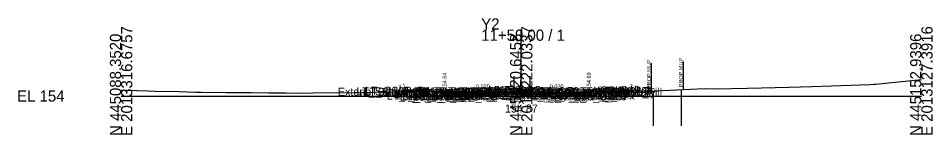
# Model space of a CAD drawing. Extents: x -26 to 203, y -10 to 6017.
# Drawn here: x -25.7 to 202.8, y 2990.3 to 3019.5 of the extents above; entities that cross this region are included whole.
import ezdxf

# ---------------------------------------------------------------- set-up
doc = ezdxf.new("R2010")
doc.units = 0
for name, color, linetype in [('Default', 7, 'Continuous'), ('Exist CMT Pavement', 7, 'Continuous'), ('Exist Cross Section Cell', 7, 'Continuous'), ('Exist XS Center Line Elevation Label', 7, 'Continuous'), ('Exist XS Ground Line', 7, 'Continuous'), ('Prop CMT Conc Surface', 7, 'Continuous'), ('Prop CMT Concrete Structures', 7, 'Continuous'), ('Prop CMT Pvmt Course 1', 7, 'Continuous'), ('Prop CMT Pvmt Course 1 CG', 7, 'Continuous'), ('Prop CMT Pvmt Course 1 Wedge', 7, 'Continuous'), ('Prop CMT Pvmt Course 2', 7, 'Continuous'), ('Prop CMT Pvmt Course 3', 7, 'Continuous'), ('Prop CMT Pvmt Surface', 7, 'Continuous'), ('Prop CMT Pvmt Wedge Surface 1', 7, 'Continuous'), ('Prop CMT Pvmt Wedge Surface 2', 7, 'Continuous'), ('Prop CMT Pvmt Wedge Surface 3', 7, 'Continuous'), ('Prop CMT Slope Grass', 7, 'Continuous'), ('Prop CMT Subgrade Earthwork', 7, 'Continuous'), ('Prop XS Earthwork Shape', 7, 'Continuous'), ('Prop XS Hydro Elevations', 7, 'Continuous'), ('Prop XS Label Text', 7, 'Continuous'), ('Prop XS SE Text', 7, 'Continuous'), ('Prop XS Side Slope Text', 7, 'Continuous'), ('Scratch_Level_0', 7, 'Continuous'), ('Scratch_Level_1', 7, 'Continuous'), ('Scratch_Level_3', 7, 'Continuous')]:
    doc.layers.add(name, color=color, linetype=linetype)

msp = doc.modelspace()

# ---------------------------------------------------------------- linework, layer by layer
at = {"layer": 'Exist CMT Pavement'}
for points in [[(98.12, 3000.89), (94.75, 3000.92), (94.58, 3000.92), (94.58, 3000.92)], [(102.81, 3000.85), (104.54, 3000.84), (113.53, 3000.87), (113.89, 3000.87)]]:
    msp.add_lwpolyline(points, dxfattribs=at)
at = {"layer": 'Exist Cross Section Cell'}
for p, q in [((100, 3000), (100, 3016.62)), ((0, 3000), (100, 3000)), ((100, 3000), (200, 3000))]:
    msp.add_line(p, q, dxfattribs=at)
at = {"layer": 'Exist XS Ground Line'}
msp.add_lwpolyline([(0, 3001.46), (1.27, 3001.43), (6.63, 3001.26), (8.46, 3001.2), (14.51, 3001.1), (18.68, 3000.96), (19.18, 3000.95), (20.04, 3000.95), (26.33, 3000.85), (27.65, 3000.85), (32.51, 3000.84), (36.8, 3000.76), (41.05, 3000.77), (44.21, 3000.75), (48, 3000.77), (60.19, 3000.87), (61.79, 3000.9), (63.21, 3000.94), (69.67, 3001.06), (71.87, 3001.1), (77.54, 3001.08), (92.24, 3001.2), (92.71, 3001.2), (94.58, 3000.92), (100, 3000.87), (104.54, 3000.84), (113.53, 3000.87), (114.15, 3000.87), (116.11, 3001.12), (116.88, 3001.12), (122.29, 3001.02), (123.96, 3001.02), (129.63, 3001.02), (135.36, 3001.36), (145.84, 3001.86), (148.45, 3001.82), (156.56, 3001.93), (166.97, 3002.21), (172.6, 3002.42), (177.54, 3002.56), (187.09, 3002.9), (188.11, 3002.94), (188.58, 3002.99), (200, 3004.17)], dxfattribs=at)
at = {"layer": 'Prop CMT Conc Surface'}
for points in [[(80.83, 3000.64), (80.83, 3001.14), (80.33, 3001.14)], [(82.83, 3000.76), (80.83, 3000.64)], [(114.89, 3000.81), (116.89, 3000.69)], [(116.89, 3000.69), (116.89, 3001.19), (117.39, 3001.19)]]:
    msp.add_lwpolyline(points, dxfattribs=at)
at = {"layer": 'Prop CMT Concrete Structures'}
for p, q in [((98.23, 3001.24), (98.22, 3001.07)), ((98.98, 3001.49), (98.23, 3001.24)), ((100.33, 3001.51), (98.98, 3001.49)), ((101.47, 3001.48), (100.33, 3001.51)), ((102.22, 3001.23), (101.47, 3001.48)), ((102.23, 3001.06), (102.22, 3001.23))]:
    msp.add_line(p, q, dxfattribs=at)
for points in [[(82.83, 3000.76), (80.83, 3000.64), (80.83, 3001.14), (80.33, 3001.14)], [(80.33, 3001.14), (80.33, 3000.13), (82.83, 3000.18)], [(82.83, 3000.18), (82.83, 3000.76)], [(98.22, 3001.07), (102.23, 3001.06)], [(114.89, 3000.81), (116.89, 3000.69), (116.89, 3001.19), (117.39, 3001.19)], [(117.39, 3001.19), (117.39, 3000.17), (114.89, 3000.22)], [(114.89, 3000.22), (114.89, 3000.81)]]:
    msp.add_lwpolyline(points, dxfattribs=at)
at = {"layer": 'Prop CMT Pvmt Course 1'}
for points in [[(98.22, 3001.07), (82.83, 3000.76)], [(82.83, 3000.76), (82.83, 3000.51)], [(82.83, 3000.51), (94.58, 3000.75)], [(94.58, 3000.87), (98.22, 3000.94)], [(94.58, 3000.75), (94.58, 3000.87)], [(98.22, 3000.82), (98.22, 3001.07)], [(98.22, 3001.07), (102.23, 3001.06)], [(98.22, 3000.82), (98.22, 3001.07)], [(98.22, 3000.94), (98.22, 3000.82), (98.22, 3000.82)], [(102.23, 3001.06), (114.89, 3000.81)], [(102.23, 3000.81), (102.23, 3001.06)], [(102.23, 3001.06), (102.23, 3000.81)], [(113.89, 3000.7), (102.23, 3000.93)], [(102.23, 3000.93), (102.23, 3000.81), (102.23, 3000.81)], [(113.89, 3000.58), (113.89, 3000.7)], [(114.89, 3000.81), (114.89, 3000.56)], [(114.89, 3000.56), (113.89, 3000.58)]]:
    msp.add_lwpolyline(points, dxfattribs=at)
at = {"layer": 'Prop CMT Pvmt Course 1 CG'}
for p, q in [((79.58, 2999.86), (82.83, 2999.84)), ((118.15, 2999.91), (114.89, 2999.89))]:
    msp.add_line(p, q, dxfattribs=at)
for points in [[(82.83, 3000.18), (79.83, 3000.12), (79.58, 2999.86)], [(82.83, 2999.93), (82.83, 3000.18)], [(114.89, 3000.22), (117.89, 3000.16), (118.15, 2999.91)], [(114.89, 2999.97), (114.89, 3000.22)]]:
    msp.add_lwpolyline(points, dxfattribs=at)
at = {"layer": 'Prop CMT Pvmt Course 1 Wedge'}
for points in [[(96.23, 3000.9), (98.12, 3000.94)], [(98.12, 3000.89), (96.23, 3000.9)], [(98.22, 3000.94), (98.22, 3000.89)], [(102.23, 3000.86), (102.23, 3000.93)], [(102.81, 3000.92), (104.54, 3000.89), (106.78, 3000.84)], [(106.78, 3000.84), (104.54, 3000.84), (102.81, 3000.85)]]:
    msp.add_lwpolyline(points, dxfattribs=at)
at = {"layer": 'Prop CMT Pvmt Course 2'}
for points in [[(92.71, 3000.71), (82.83, 3000.51)], [(94.58, 3000.41), (94.58, 3000.75)], [(98.22, 3000.49), (98.22, 3000.82)], [(102.23, 3000.81), (102.23, 3000.48)], [(82.83, 3000.51), (82.83, 3000.18)], [(82.83, 3000.18), (92.71, 3000.38)], [(113.89, 3000.24), (113.89, 3000.58)], [(113.89, 3000.58), (114.89, 3000.56)], [(114.89, 3000.22), (113.89, 3000.24)], [(114.89, 3000.56), (114.89, 3000.22)]]:
    msp.add_lwpolyline(points, dxfattribs=at)
at = {"layer": 'Prop CMT Pvmt Course 3'}
for points in [[(94.58, 3000.41), (82.83, 3000.18)], [(82.83, 3000.18), (82.83, 2999.84)], [(82.83, 2999.84), (94.58, 3000.08)], [(94.58, 3000.08), (94.58, 3000.41)], [(113.89, 3000.24), (114.89, 3000.22)], [(113.89, 2999.91), (113.89, 3000.24)], [(114.89, 2999.89), (113.89, 2999.91)], [(114.89, 3000.22), (114.89, 2999.89)]]:
    msp.add_lwpolyline(points, dxfattribs=at)
at = {"layer": 'Prop CMT Pvmt Surface'}
for points in [[(98.22, 3001.07), (82.83, 3000.76)], [(98.22, 3001.07), (102.23, 3001.06)], [(102.23, 3001.06), (114.89, 3000.81)]]:
    msp.add_lwpolyline(points, dxfattribs=at)
at = {"layer": 'Prop CMT Pvmt Wedge Surface 1'}
for points in [[(82.83, 3000.51), (82.83, 3000.76)], [(82.83, 3000.51), (82.83, 3000.76)], [(92.71, 3000.71), (82.83, 3000.51)], [(92.71, 3000.71), (82.83, 3000.51)], [(98.22, 3000.94), (94.58, 3000.87)], [(98.22, 3000.94), (94.58, 3000.87)], [(94.58, 3000.87), (94.58, 3000.75)], [(94.58, 3000.87), (94.58, 3000.75)], [(98.22, 3001.07), (98.22, 3000.82), (98.22, 3000.82), (98.22, 3000.94)], [(102.23, 3001.06), (102.23, 3000.81), (102.23, 3000.81), (102.23, 3000.93)], [(102.23, 3000.93), (113.89, 3000.7)], [(102.23, 3000.93), (113.89, 3000.7)], [(113.89, 3000.7), (113.89, 3000.58)], [(113.89, 3000.7), (113.89, 3000.58)], [(114.89, 3000.56), (114.89, 3000.81)], [(114.89, 3000.56), (114.89, 3000.81)], [(113.89, 3000.58), (114.89, 3000.56)], [(113.89, 3000.58), (114.89, 3000.56)]]:
    msp.add_lwpolyline(points, dxfattribs=at)
at = {"layer": 'Prop CMT Pvmt Wedge Surface 2'}
for points in [[(82.83, 3000.51), (82.83, 3000.76)], [(82.83, 3000.51), (82.83, 3000.76)], [(98.22, 3000.82), (94.58, 3000.75)], [(98.22, 3000.82), (94.58, 3000.75)], [(98.22, 3001.07), (98.22, 3000.82)], [(102.23, 3000.81), (98.22, 3000.82)], [(102.23, 3001.06), (102.23, 3000.81)], [(102.23, 3000.81), (114.89, 3000.56)], [(102.23, 3000.81), (114.89, 3000.56)], [(114.89, 3000.56), (114.89, 3000.81)], [(114.89, 3000.56), (114.89, 3000.81)]]:
    msp.add_lwpolyline(points, dxfattribs=at)
at = {"layer": 'Prop CMT Pvmt Wedge Surface 3'}
for points in [[(82.83, 3000.18), (82.83, 3000.76)], [(82.83, 3000.18), (82.83, 3000.76)], [(98.22, 3001.07), (98.22, 3000.49)], [(102.23, 3001.06), (102.23, 3000.48)], [(114.89, 3000.22), (114.89, 3000.81)], [(114.89, 3000.22), (114.89, 3000.81)], [(98.22, 3000.49), (94.58, 3000.41)], [(98.22, 3000.49), (94.58, 3000.41)], [(102.23, 3000.48), (98.22, 3000.49)], [(102.23, 3000.48), (114.89, 3000.22)], [(102.23, 3000.48), (114.89, 3000.22)]]:
    msp.add_lwpolyline(points, dxfattribs=at)
at = {"layer": 'Prop CMT Slope Grass'}
for points in [[(80.33, 3001.14), (70.83, 3001.33), (70.03, 3001.07)], [(117.39, 3001.19), (126.39, 3001.37)], [(126.39, 3001.37), (126.89, 3001.38), (127.97, 3001.02)]]:
    msp.add_lwpolyline(points, dxfattribs=at)
at = {"layer": 'Prop CMT Subgrade Earthwork'}
msp.add_line((94.58, 3000.92), (94.58, 3000.08), dxfattribs=at)
for points in [[(82.83, 2999.84), (79.58, 2999.86), (78.26, 3001.18)], [(82.83, 2999.84), (79.58, 2999.86), (78.26, 3001.18)], [(113.89, 2999.91), (113.88, 3000.87)], [(114.89, 2999.89), (118.15, 2999.91), (119.47, 3001.23)], [(114.89, 2999.89), (118.15, 2999.91), (119.47, 3001.23)], [(94.58, 3000.08), (82.83, 2999.84)], [(113.89, 2999.91), (114.89, 2999.89)]]:
    msp.add_lwpolyline(points, dxfattribs=at)
at = {"layer": 'Prop XS Earthwork Shape'}
for points in [[(78.35, 3001.09), (78.26, 3001.18), (70.83, 3001.33), (70.03, 3001.07), (71.87, 3001.1), (77.54, 3001.08)], [(78.35, 3001.09), (78.26, 3001.18), (70.83, 3001.33), (70.03, 3001.07), (71.87, 3001.1), (77.54, 3001.08)], [(78.35, 3001.09), (78.26, 3001.18), (70.83, 3001.33), (70.03, 3001.07), (71.87, 3001.1), (77.54, 3001.08)], [(70.03, 3001.07), (71.87, 3001.1), (77.54, 3001.08), (78.35, 3001.09), (78.26, 3001.18), (70.83, 3001.33)], [(78.35, 3001.09), (80.33, 3001.1), (80.33, 3000.13), (82.83, 3000.18), (82.83, 3000.76), (94.12, 3000.99), (94.58, 3000.92), (94.58, 3000.08), (82.83, 2999.84), (79.58, 2999.86)], [(78.35, 3001.09), (80.33, 3001.1), (80.33, 3000.13), (82.83, 3000.18), (82.83, 3000.76), (94.12, 3000.99), (94.58, 3000.92), (94.58, 3000.08), (82.83, 2999.84), (79.58, 2999.86)], [(78.35, 3001.09), (80.33, 3001.1), (80.33, 3000.13), (82.83, 3000.18), (82.83, 3000.76), (94.12, 3000.99), (94.58, 3000.92), (94.58, 3000.08), (82.83, 2999.84), (79.58, 2999.86)], [(78.35, 3001.09), (80.33, 3001.1), (80.33, 3000.13), (82.83, 3000.18), (82.83, 3000.76), (94.12, 3000.99), (94.58, 3000.92), (94.58, 3000.08), (82.83, 2999.84), (79.58, 2999.86)], [(82.83, 3000.76), (80.83, 3000.64), (80.83, 3001.11), (80.33, 3001.1), (80.33, 3000.13), (82.83, 3000.18)], [(82.83, 3000.76), (80.83, 3000.64), (80.83, 3001.11), (80.33, 3001.1), (80.33, 3000.13), (82.83, 3000.18)], [(82.83, 3000.76), (80.83, 3000.64), (80.83, 3001.11), (80.33, 3001.1), (80.33, 3000.13), (82.83, 3000.18)], [(82.83, 3000.76), (80.83, 3000.64), (80.83, 3001.11), (80.33, 3001.1), (80.33, 3000.13), (82.83, 3000.18)], [(82.83, 3000.76), (80.83, 3000.64), (80.83, 3001.11), (92.24, 3001.2), (92.71, 3001.2), (94.12, 3000.99)], [(82.83, 3000.76), (80.83, 3000.64), (80.83, 3001.11), (92.24, 3001.2), (92.71, 3001.2), (94.12, 3000.99)], [(82.83, 3000.76), (80.83, 3000.64), (80.83, 3001.11), (92.24, 3001.2), (92.71, 3001.2), (94.12, 3000.99)], [(82.83, 3000.76), (80.83, 3000.64), (80.83, 3001.11), (92.24, 3001.2), (92.71, 3001.2), (94.12, 3000.99)], [(112.01, 3000.86), (113.88, 3000.83), (113.88, 3000.87), (113.53, 3000.87)], [(112.01, 3000.86), (113.88, 3000.83), (113.88, 3000.87), (113.53, 3000.87)], [(112.01, 3000.86), (113.88, 3000.83), (113.88, 3000.87), (113.53, 3000.87)], [(112.01, 3000.86), (113.88, 3000.83), (113.88, 3000.87), (113.53, 3000.87)], [(114.89, 3000.81), (116.89, 3000.69), (116.89, 3001.12), (116.88, 3001.12), (116.11, 3001.12), (114.15, 3000.87), (113.89, 3000.87), (113.88, 3000.87), (113.88, 3000.83)], [(114.89, 3000.81), (116.89, 3000.69), (116.89, 3001.12), (116.88, 3001.12), (116.11, 3001.12), (114.15, 3000.87), (113.89, 3000.87), (113.88, 3000.87), (113.88, 3000.83)], [(114.89, 3000.81), (116.89, 3000.69), (116.89, 3001.12), (116.88, 3001.12), (116.11, 3001.12), (114.15, 3000.87), (113.89, 3000.87), (113.88, 3000.87), (113.88, 3000.83)], [(114.89, 3000.81), (116.89, 3000.69), (116.89, 3001.12), (116.88, 3001.12), (116.11, 3001.12), (114.15, 3000.87), (113.89, 3000.87), (113.88, 3000.87), (113.88, 3000.83)], [(117.39, 3001.11), (117.39, 3000.17), (114.89, 3000.22), (114.89, 3000.81), (113.88, 3000.83), (113.89, 2999.91), (114.89, 2999.89), (118.15, 2999.91), (119.31, 3001.07)], [(117.39, 3001.11), (119.31, 3001.07), (118.15, 2999.91), (114.89, 2999.89), (113.89, 2999.91), (113.88, 3000.83), (114.89, 3000.81), (114.89, 3000.22), (117.39, 3000.17)], [(117.39, 3001.11), (119.31, 3001.07), (118.15, 2999.91), (114.89, 2999.89), (113.89, 2999.91), (113.88, 3000.83), (114.89, 3000.81), (114.89, 3000.22), (117.39, 3000.17)], [(117.39, 3001.11), (119.31, 3001.07), (118.15, 2999.91), (114.89, 2999.89), (113.89, 2999.91), (113.88, 3000.83), (114.89, 3000.81), (114.89, 3000.22), (117.39, 3000.17)], [(116.89, 3001.12), (117.39, 3001.11), (117.39, 3000.17), (114.89, 3000.22), (114.89, 3000.81), (116.89, 3000.69)], [(117.39, 3001.11), (117.39, 3000.17), (114.89, 3000.22), (114.89, 3000.81), (116.89, 3000.69), (116.89, 3001.12)], [(117.39, 3001.11), (117.39, 3000.17), (114.89, 3000.22), (114.89, 3000.81), (116.89, 3000.69), (116.89, 3001.12)], [(116.89, 3001.12), (117.39, 3001.11), (117.39, 3000.17), (114.89, 3000.22), (114.89, 3000.81), (116.89, 3000.69)], [(126.39, 3001.37), (126.89, 3001.38), (127.97, 3001.02), (123.96, 3001.02), (122.29, 3001.02), (119.31, 3001.07), (119.47, 3001.23)], [(126.39, 3001.37), (126.89, 3001.38), (127.97, 3001.02), (123.96, 3001.02), (122.29, 3001.02), (119.31, 3001.07), (119.47, 3001.23)], [(126.39, 3001.37), (126.89, 3001.38), (127.97, 3001.02), (123.96, 3001.02), (122.29, 3001.02), (119.31, 3001.07), (119.47, 3001.23)], [(126.39, 3001.37), (126.89, 3001.38), (127.97, 3001.02), (123.96, 3001.02), (122.29, 3001.02), (119.31, 3001.07), (119.47, 3001.23)]]:
    msp.add_lwpolyline(points, close=True, dxfattribs=at)
at = {"layer": 'Prop XS Label Text'}
for p, q in [((132.51, 3008.19), (132.51, 3001.19)), ((140.51, 3008.6), (140.51, 3001.6))]:
    msp.add_line(p, q, dxfattribs=at)
at = {"layer": 'Scratch_Level_1'}
for p, q in [((133.01, 3001.22), (133.01, 2992.52)), ((140.01, 3001.58), (140.01, 2992.52))]:
    msp.add_line(p, q, dxfattribs=at)
at = {"layer": 'Scratch_Level_3'}
for p, q in [((98.22, 3001.07), (98.22, 3004.93)), ((102.23, 3001.07), (102.23, 3004.93))]:
    msp.add_line(p, q, dxfattribs=at)

# ---------------------------------------------------------------- texts
at = {"layer": 'Default'}
msp.add_text('-', height=0.0001, dxfattribs=at).set_placement((0, 3000))
at = {"layer": 'Exist Cross Section Cell'}
for s, p in [('Y2', (90, 3016.62)), ('11+50.00 / 1', (90, 3013.82)), ('EL 154', (-26, 2998.6))]:
    msp.add_text(s, height=2.8, dxfattribs=at).set_placement(p)
for s, p in [('E 2013316.6757', (2.8, 2990)), ('E 2013222.0337', (102.8, 2990)), ('E 2013127.3916', (202.8, 2990)), ('N 445088.3520', (0, 2990)), ('N 445120.6458', (100, 2990)), ('N 445152.9396', (200, 2990))]:
    msp.add_text(s, height=2.8, rotation=90, dxfattribs=at).set_placement(p)
at = {"layer": 'Exist XS Center Line Elevation Label'}
msp.add_text('154.87', height=2, dxfattribs=at).set_placement((95.94, 2995.87))
at = {"layer": 'Prop XS Hydro Elevations'}
for s, p in [('154.64', (81.33, 3001.64)), ('154.69', (117.39, 3001.69))]:
    msp.add_text(s, height=1, rotation=90, dxfattribs=at).set_placement(p)
at = {"layer": 'Prop XS Label Text'}
for p in [(132.41, 3001.76), (140.41, 3002.18)]:
    msp.add_text('PROP.MUP', height=1, rotation=90, dxfattribs=at).set_placement(p)
at = {"layer": 'Prop XS SE Text'}
for rotation, p in [(1.1458, (88.71, 3001.88)), (358.8542, (107.12, 3001.96))]:
    msp.add_text('0.020', height=1, rotation=rotation, dxfattribs=at).set_placement(p)
at = {"layer": 'Prop XS Side Slope Text'}
for rotation, p in [(18.4349, (69.44, 3001.66)), (341.5651, (126.91, 3002.16))]:
    msp.add_text('3:1', height=1, rotation=rotation, dxfattribs=at).set_placement(p)
at = {"layer": 'Scratch_Level_0'}
for s, p in [('Exterior Boundary', (54.18, 3000.07)), ('LT_Sub_Trench_Out_DLT', (58.82, 3000.18)), ('LT_Slope_Fill', (60.55, 3000.07)), ('LT_CSLP_Pnt', (61, 3000.33)), ('LT_CG1_Shelf_Out', (66.38, 2999.12)), ('LT_CG_Top_Face', (68.09, 3000.14)), ('LT_CG_Top_BOC', (68.61, 3000.14)), ('LT_CG_Bot_BOC', (68.65, 2999.13)), ('LT_CG_Top_Gut', (69.07, 2999.64)), ('LT_Sub_OEOP', (69.69, 2998.86)), ('LT_Sub_OEOT_CG', (70.2, 2998.93)), ('LT_CG_Bot_IE', (72.74, 2999.18)), ('LT_Sub_OEOT', (72.91, 2998.84)), ('LT_PV2_OEOT', (73, 2999.51)), ('LT_PV3_OEOT', (73, 2999.18)), ('LT_PV1_OEOT', (73.57, 2999.76)), ('LT_PV_Sub_Tie_Out', (77.67, 3000.19)), ('LT_PV_OEEOP_EG', (80.26, 3000.2)), ('LT_PV_EG_TestPt', (81.83, 2999.91)), ('LT_Sub_OEEOP', (81.92, 2999.04)), ('LT_PV2_OEEOP', (82.02, 2999.71)), ('LT_PV3_OEEOP', (82.02, 2999.38)), ('LT_PV1_OEEOP', (82.59, 2999.83)), ('LT_PV_IEEOP_EG', (86.31, 2999.89)), ('LT_PV2_IEEOP', (88.08, 2999.82)), ('LT_PV3_IEEOP', (88.08, 2999.48)), ('LT_PV1_IEEOP', (88.64, 2999.94)), ('LT_PV2_PGL1', (89.01, 2999.82)), ('LT_PV3_PGL1', (89.01, 2999.48)), ('LT_PV2_PGL', (89.34, 2999.82)), ('LT_PV3_PGL', (89.34, 2999.48)), ('LT_PV4_PGL', (89.34, 2999.15)), ('LT_PV1_PGL', (89.9, 3000.07)), ('MI_Face In', (90.02, 3000.23)), ('RT_PV_IEEOP_EG', (90.95, 2999.85)), ('MI_Top In', (91.73, 3000.48)), ('RT_PV2_IEEOP', (92.71, 2999.8)), ('RT_PV3_IEEOP', (92.71, 2999.46)), ('MI_Face Out', (93.07, 3000.21)), ('MI_Top Out', (93.28, 3000.46)), ('RT_PV1_IEEOP', (93.28, 2999.92)), ('MI_Crown', (93.54, 3000.52)), ('RT_PV2_PGL1', (93.64, 2999.8)), ('RT_PV3_PGL1', (93.64, 2999.46)), ('RT_PV2_PGL', (93.97, 2999.8)), ('RT_PV3_PGL', (93.97, 2999.46)), ('RT_PV4_PGL', (93.97, 2999.13)), ('MI_Bot Out', (94.07, 3000.05)), ('RT_PV1_PGL', (94.54, 3000.05)), ('RT_PV_EG_TestPt', (94.71, 2999.85)), ('RT_PV_Sub_Tie_Out', (98.77, 2999.87)), ('RT_Sub_Trench_Out_DLT', (99.99, 3000.23)), ('RT_PV_OEEOP_EG', (101.39, 2999.87)), ('RT_Sub_OEOT_CG', (102.21, 2998.97)), ('RT_Sub_OEEOP', (103.06, 2998.91)), ('RT_PV2_OEEOP', (103.15, 2999.58)), ('RT_PV3_OEEOP', (103.15, 2999.24)), ('RT_PV1_OEEOP', (103.72, 2999.7)), ('RT_CG_Top_Face', (104.1, 3000.19)), ('RT_CG1_Shelf_Out', (104.39, 2999.16)), ('RT_CG_Bot_IE', (104.76, 2999.22)), ('RT_Sub_OEOT', (104.92, 2998.89)), ('RT_PV2_OEOT', (105.02, 2999.56)), ('RT_PV3_OEOT', (105.02, 2999.22)), ('RT_CG_Top_Gut', (105.08, 2999.69)), ('RT_PV1_OEOT', (105.58, 2999.81)), ('RT_CG_Top_BOC', (105.63, 3000.19)), ('RT_CG_Bot_BOC', (105.66, 2999.17)), ('RT_Sub_OEOP', (108.21, 2998.91)), ('Exterior Boundary', (112.11, 3000.02)), ('RT_Slope_Fill', (118.44, 3000.02)), ('RT_Shld_O', (118.93, 3000.37)), ('CSLP_Pnt', (119.76, 3000.38))]:
    msp.add_text(s, height=2, dxfattribs=at).set_placement(p)

doc.saveas('drawing.dxf')
